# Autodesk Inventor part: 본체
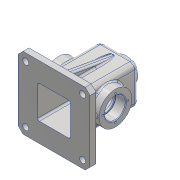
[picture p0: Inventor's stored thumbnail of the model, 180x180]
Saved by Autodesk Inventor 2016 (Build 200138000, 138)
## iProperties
Created: 2018-10
Part Number: 본체
Material: 알루미늄 6061
Document SubType Name: Modeling
Designer: user
Density: 2.7 g/cm^3
Appearance: 알루미늄 - 평지
Mass: 793.695 g
Surface Area: 900.75 cm^2
Volume: 293.961 cm^3
Author: user
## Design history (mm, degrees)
sketch "스케치1"
  geometry: L1 (60, 60)-(-60, 60); L2 (-60, 60)-(-60, -60); L3 (-60, -60)-(60, -60); L4 (60, -60)-(60, 60); L5 (60, 60)-(-60, -60); L6 (-60, 60)-(60, -60); 1 further point
  constraints: 12 end point, 2 midpoint, 2 parallel, 1 horizontal, 1 perpendicular
  dimensions: "d0" = 120 distance of L3.end L2.end; "d1" = 120 distance of L2.end L1.end
extrude "돌출1" new body sketch "스케치1" distance "d2" = 10; taper "d3" = 0 deg
sketch "스케치2"
  geometry: L1 (-32.5, -32.5)-(32.5, -32.5); L2 (32.5, -32.5)-(32.5, 32.5); L3 (32.5, 32.5)-(-32.5, 32.5); L4 (-32.5, 32.5)-(-32.5, -32.5); L5 (-32.5, -32.5)-(32.5, 32.5); L6 (32.5, -32.5)-(-32.5, 32.5); 1 further point
  constraints: 12 end point, 2 midpoint, 2 parallel, 1 horizontal, 1 perpendicular
  dimensions: "d4" = 65 distance of L3.end L2.end; "d5" = 65 distance of L2.end L1.end
extrude "돌출2" join sketch "스케치2" distance "d6" = 100; taper "d7" = 0 deg
sketch "스케치4"
  geometry: L1 (92.5, -10)-(-27.5, -10) reference; L2 (-27.5, 0)-(92.5, 0) reference; C1 r 27.5 at (32.5, 45); 2 further points
  constraints: 1 centre point, 1 midpoint, 1 vertical alignment
  dimensions: "d11" = 55 diameter of C1; "d12" = 55 distance from line of L1 C1.centre
extrude "돌출4" join sketch "스케치4" distance "d13" = 15; taper "d14" = 0 deg
sketch "스케치5"
  geometry: L1 (-27.5, -27.5)-(27.5, -27.5); L2 (27.5, -27.5)-(27.5, 27.5); L3 (27.5, 27.5)-(-27.5, 27.5); L4 (-27.5, 27.5)-(-27.5, -27.5); L5 (-27.5, -27.5)-(27.5, 27.5); L6 (27.5, -27.5)-(-27.5, 27.5); 1 further point
  constraints: 12 end point, 2 midpoint, 2 parallel, 1 horizontal, 1 perpendicular
  dimensions: "d15" = 55 distance of L3.end L2.end; "d16" = 55 distance of L2.end L1.end
extrude "돌출5" cut sketch "스케치5" distance "d17" = 105; taper "d18" = 0 deg
sketch "스케치6"
  geometry: C1 r 27.5 at (0, 0) reference; C2 r 17.5 at (0, 0); 1 further point
  constraints: 1 centre point, 1 coincident
  dimensions: "d19" = 35 diameter of C2
extrude "돌출6" cut sketch "스케치6" distance "d20" = 17; taper "d21" = 0 deg
sketch "스케치7"
  geometry: C1 r 17.5 at (0, 0) reference; C2 r 15 at (0, 0); 1 further point
  constraints: 1 centre point, 1 coincident
  dimensions: "d22" = 30 diameter of C2
extrude "돌출7" cut sketch "스케치7" distance "d23" = 3; taper "d24" = 0 deg
sketch "스케치9"
  geometry: L1 (0, 48)-(87.905, 32.5); L2 (0, 32.5)-(100, 32.5) reference; L3 (0, 60)-(-10, 60) reference; L4 (0, 60)-(0, -60) reference; 1 further point
  constraints: 2 end point, 2 point on line
  dimensions: "d25" = 10 deg angle of L3 L1; "d26" = 12 distance from line of L3 L1.start
extrude "돌출8" join sketch "스케치9" stored distance "d27" = 10; taper "d28" = 0 deg
sketch "스케치10"
  geometry: L1 (65, 0)-(0, 0) reference; L2 (0, 0)-(0, 100) reference; L3 (0, 100)-(65, 100) reference; L4 (65, 100)-(65, 0) reference; L5 (65, 0)-(92.5, 0) reference; L6 (92.5, 0)-(92.5, -10) reference; L7 (92.5, -10)-(-27.5, -10) reference; L8 (-27.5, -10)-(-27.5, 0) reference; L9 (-27.5, 0)-(0, 0) reference; L10 (0, 0)-(65, 0) reference; L11 (0, 0)-(65, 0) reference; L12 (29.5, 0)-(35.5, 0); L13 (35.5, 0)-(35.5, 22.106); L14 (35.5, 22.106)-(29.5, 22.106); L15 (29.5, 22.106)-(29.5, 0); C1 r 17.5 at (32.5, 45) reference; C2 r 27.5 at (32.5, 45) reference; 3 further points
  constraints: 8 end point, 2 midpoint, 2 parallel, 1 horizontal, 1 perpendicular, 1 point on line, 1 vertical alignment
  dimensions: "d29" = 6 distance of L13.end L14.end
extrude "돌출9" join sketch "스케치10" distance "d30" = 10; taper "d31" = 0 deg
sketch "스케치11"
  geometry: L1 (-47.5, -47.5)-(47.5, -47.5); L2 (47.5, -47.5)-(47.5, 47.5); L3 (47.5, 47.5)-(-47.5, 47.5); L4 (-47.5, 47.5)-(-47.5, -47.5); L5 (-47.5, -47.5)-(47.5, 47.5); L6 (47.5, -47.5)-(-47.5, 47.5); 5 further points
  constraints: 12 end point, 4 coincident, 2 midpoint, 2 parallel, 1 horizontal, 1 perpendicular
  dimensions: "d33" = 95 distance of L3.end L2.end; "d34" = 95 distance of L2.end L1.end
hole "구멍1" sketch "스케치11" at (-47.5, 47.5), (47.5, 47.5), (47.5, -47.5), (-47.5, -47.5) diameter "d35" = 10; stored, may be unused: countersink angle "d39" = 90 deg, drill point angle "d41" = 118 deg; dims "d36" = 6, "d37" = 4, "d38" = 2, "d40" = 8
chamfer "모따기1" distance "d42" = 8; stored, may be unused: second distance "d43" = 2, angle "d44" = 45 deg
fillet "모깎기1" dims "d52" = 8
fillet "모깎기2" dims "d53" = 8
sketch "스케치13" dims "d54" = 42
  geometry: C1 r 17.5 at (0, 0) reference; C2 r 27.5 at (0, 0) reference; 3 further points
  constraints: 2 vertical alignment, 1 coincident, 2 other
hole "구멍3" sketch "스케치13" at (0, 21) diameter "d55" = 3.242; stored, may be unused: countersink angle "d59" = 90 deg, drill point angle "d61" = 118 deg; dims "d56" = 8, "d57" = 4, "d58" = 2, "d60" = 10
node "작업 평면1"
sketch "스케치14"
  geometry: C1 r 20 at (0, 0); 1 further point
  constraints: 1 centre point, 1 coincident
  dimensions: "d66" = 40 diameter of C1
extrude "돌출10" join sketch "스케치14" distance "d67" = 10; taper "d68" = 7 deg
sketch "스케치15"
  geometry: C1 r 20 at (0, 0) reference; C2 r 20 at (0, 0) reference; C3 r 20 at (0, 0) reference; 1 further point
  constraints: 2 coincident
hole "구멍4" sketch "스케치15" at (0, 0) diameter "d69" = 22.835; stored, may be unused: countersink angle "d73" = 90 deg, drill point angle "d75" = 118 deg; dims "d70" = 50, "d71" = 4, "d72" = 2, "d74" = 59.3
fillet "모깎기3" dims "d76" = 3
fillet "모깎기4" dims "d77" = 3
fillet "모깎기5" dims "d78" = 3
fillet "모깎기6" dims "d79" = 3
fillet "모깎기10" dims "d83" = 0.3
chamfer "모따기2" distance "d84" = 1; stored, may be unused: second distance "d85" = 2, angle "d86" = 45 deg
fillet "모깎기11" dims "d87" = 3
fillet "모깎기12" dims "d88" = 3
sketch "스케치16"
  geometry: L1 (4.5, 18)-(44.5, 18) reference; 3 further points
  constraints: 1 midpoint, 1 vertical alignment, 1 other
  dimensions: "d89" = 26 distance from line of L1 point (24.5, -8)
feature "엠보싱1" sketch "스케치16" dims "d90" = 0.5, "d91" = 0
fillet "모깎기13" dims "d92" = 3
fillet "모깎기14" dims "d93" = 3
fillet "모깎기15" dims "d94" = 1
node "솔리드1"
mirror "대칭1"
mirror "대칭2"
mirror "대칭3"
mirror "대칭4"
pattern_circular "원형 패턴1" dims angle "d63" = 360 deg
mirror "대칭5"
node "절단 모서리 투영1"
node "절단 모서리 투영2"
node "절단 모서리 투영3"
